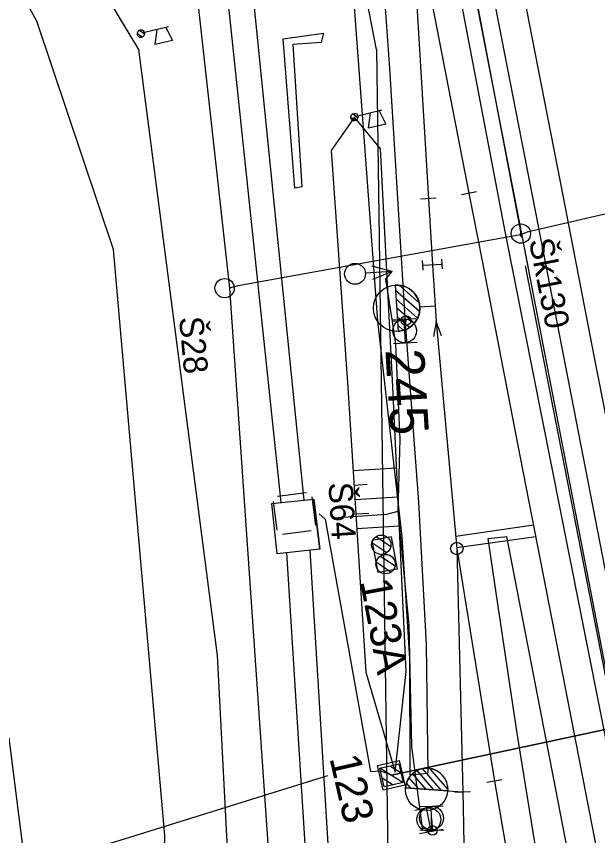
# Model space of a CAD drawing. Extents: x -545846 to -545044, y -1122650 to -1119108.
# Drawn here: x -545637.44 to -545607.35, y -1119789.85 to -1119747.46 of the extents above; entities that cross this region are included whole.
import ezdxf

# ---------------------------------------------------------------- set-up
doc = ezdxf.new("R2010")
doc.units = 0
for name, color, linetype in [('osvětlené plochy-hodnota-obrys', 7, 'Continuous'), ('Vrstva 1', 7, 'Continuous'), ('Vrstva 1 - Koleje', 7, 'Continuous'), ('Vrstva 11 - Trakce', 7, 'Continuous'), ('Vrstva 12 - Trakce zaklady', 7, 'Continuous'), ('Vrstva 17', 7, 'Continuous'), ('Vrstva 2', 7, 'Continuous'), ('Vrstva 2 - Vyhybky', 7, 'Continuous'), ('Vrstva 25', 7, 'Continuous'), ('Vrstva 26', 7, 'Continuous'), ('Vrstva 27', 7, 'Continuous'), ('Vrstva 28 - zabzar', 7, 'Continuous'), ('Vrstva 3', 7, 'Continuous'), ('Vrstva 3 - Lisy - Pocitaci body', 7, 'Continuous'), ('Vrstva 33', 7, 'Continuous'), ('Vrstva 34', 7, 'Continuous'), ('Vrstva 35', 7, 'Continuous'), ('Vrstva 36', 7, 'Continuous'), ('Vrstva 4 - Teren - stezky - prechody - plochy', 7, 'Continuous'), ('Vrstva 43', 7, 'Continuous'), ('Vrstva 44', 7, 'Continuous'), ('Vrstva 48', 7, 'Continuous'), ('Vrstva 49', 7, 'Continuous'), ('Vrstva 62', 7, 'Continuous'), ('Vrstva 63', 7, 'Continuous'), ('Vrstva 7 - Namezniky-vystroj', 7, 'Continuous')]:
    doc.layers.add(name, color=color, linetype=linetype)

msp = doc.modelspace()

# ---------------------------------------------------------------- linework, layer by layer
at = {"layer": 'osvětlené plochy-hodnota-obrys'}
for points in [[(-545610.895, -1119760.665), (-545622.836, -1119699.488), (-545637.26, -1119626.872), (-545653.542, -1119543.449), (-545716.386, -1119223.717)], [(-545618.794, -1119749.17), (-545664.282, -1119515.639)], [(-545618.794, -1119749.17), (-545617.001, -1119876.724)], [(-545611.105, -1119760.367), (-545492.389, -1120368.615), (-545475.582, -1120447.487)]]:
    msp.add_lwpolyline(points, dxfattribs=at)
at = {"layer": 'Vrstva 1'}
for points in [[(-545612.685, -1119787.025), (-545611.094, -1119796.357), (-545607.898, -1119813.098), (-545602.376, -1119841.635), (-545599.033, -1119858.8), (-545594.075, -1119884.173), (-545590.564, -1119902.118), (-545586.815, -1119921.29), (-545582.879, -1119941.487), (-545579.286, -1119959.902), (-545575.686, -1119978.306), (-545572.135, -1119996.454), (-545569.055, -1120012.422), (-545565.503, -1120030.558), (-545561.469, -1120051.222), (-545557.681, -1120070.616), (-545552.89, -1120095.213)], [(-545614.338, -1119787.583), (-545614.32, -1119788.383), (-545614.101, -1119799.744), (-545613.855, -1119812.402)]]:
    msp.add_lwpolyline(points, dxfattribs=at)
at = {"layer": 'Vrstva 1 - Koleje'}
for points in [[(-545620.04, -1119700.93), (-545618.466, -1119708.981), (-545618.287, -1119709.904), (-545617.707, -1119712.885), (-545616.218, -1119720.514), (-545614.817, -1119727.693), (-545612.814, -1119737.973), (-545610.755, -1119748.533), (-545609.137, -1119756.825), (-545607.54, -1119765.023), (-545606.208, -1119771.849), (-545604.163, -1119782.329), (-545602.108, -1119792.879), (-545600.005, -1119803.67), (-545598.048, -1119813.712), (-545596.051, -1119823.937), (-545594.041, -1119834.228), (-545591.245, -1119848.57), (-545589.268, -1119858.708), (-545587.271, -1119868.949), (-545585.312, -1119878.984), (-545583.448, -1119888.544), (-545581.461, -1119898.732)], [(-545619.495, -1119728.51), (-545619.342, -1119729.295), (-545617.081, -1119740.889), (-545616.115, -1119756.897), (-545615.896, -1119760.311), (-545615.76, -1119762.434)], [(-545619.495, -1119728.51), (-545619.342, -1119729.295), (-545617.081, -1119740.889), (-545614.014, -1119756.616), (-545613.347, -1119760.026), (-545611.356, -1119770.277), (-545609.291, -1119780.868), (-545607.284, -1119791.169), (-545605.791, -1119798.836), (-545605.539, -1119800.128), (-545603.55, -1119810.316), (-545601.73, -1119819.637), (-545599.797, -1119829.553), (-545597.8, -1119839.791), (-545595.924, -1119849.399), (-545593.688, -1119860.879), (-545591.957, -1119869.777), (-545589.995, -1119879.817), (-545588.126, -1119889.394), (-545586.206, -1119899.252)], [(-545615.76, -1119762.434), (-545615.705, -1119763.242), (-545614.641, -1119774.995), (-545612.699, -1119787.025)], [(-545615.76, -1119762.434), (-545615.705, -1119763.242), (-545614.641, -1119774.995), (-545614.338, -1119787.597)]]:
    msp.add_lwpolyline(points, dxfattribs=at)
at = {"layer": 'Vrstva 11 - Trakce'}
for p, q in [((-545619.036, -1119774.681), (-545618.272, -1119775.204)), ((-545618.818, -1119774.376), (-545618.065, -1119774.892)), ((-545618.592, -1119775.381), (-545617.839, -1119775.897)), ((-545618.81, -1119775.686), (-545618.046, -1119776.209)), ((-545618.618, -1119786.347), (-545617.425, -1119787.099)), ((-545618.102, -1119786.23), (-545617.543, -1119786.582)), ((-545618.505, -1119786.862), (-545617.939, -1119787.219))]:
    msp.add_line(p, q, dxfattribs=at)
msp.add_lwpolyline([(-545549.18, -1119771.986), (-545573.653, -1119777.088), (-545592.324, -1119781.23), (-545618.023, -1119786.725)], dxfattribs=at)
msp.add_lwpolyline([(-545617.646, -1119786.127), (-545617.425, -1119787.102), (-545618.4, -1119787.323), (-545618.621, -1119786.348)], close=True, dxfattribs=at)
for centre in [(-545618.553, -1119774.795), (-545618.327, -1119775.8)]:
    msp.add_circle(centre, 0.5, dxfattribs=at)
at = {"layer": 'Vrstva 12 - Trakce zaklady'}
for p, q in [((-545618.038, -1119774.387), (-545619.021, -1119774.57)), ((-545618.71, -1119776.236), (-545619.021, -1119774.57)), ((-545618.038, -1119774.387), (-545617.727, -1119776.053)), ((-545617.727, -1119776.053), (-545618.71, -1119776.236)), ((-545618.744, -1119786.214), (-545617.624, -1119785.963)), ((-545617.333, -1119787.239), (-545618.454, -1119787.491))]:
    msp.add_line(p, q, dxfattribs=at)
for points in [[(-545618.744, -1119786.214), (-545617.624, -1119785.963), (-545617.333, -1119787.239), (-545618.454, -1119787.491), (-545618.744, -1119786.214)], [(-545617.624, -1119785.963), (-545617.624, -1119785.963), (-545617.333, -1119787.239), (-545617.333, -1119787.239)]]:
    msp.add_lwpolyline(points, dxfattribs=at)
at = {"layer": 'Vrstva 17'}
msp.add_lwpolyline([(-545622.664, -1119756.289), (-545623.027, -1119756.353), (-545623.639, -1119748.623), (-545621.55, -1119748.325), (-545621.666, -1119748.822), (-545623.125, -1119748.912)], close=True, dxfattribs=at)
at = {"layer": 'Vrstva 2'}
for p, q in [((-545615.823, -1119787.482), (-545616.697, -1119786.477)), ((-545615.426, -1119787.51), (-545616.41, -1119786.379)), ((-545615.108, -1119787.447), (-545616.042, -1119786.372)), ((-545616.616, -1119787.426), (-545617.116, -1119786.852)), ((-545616.22, -1119787.454), (-545616.931, -1119786.637)), ((-545615.108, -1119787.532), (-545617.298, -1119787.379)), ((-545617.298, -1119787.379), (-545615.108, -1119787.531)), ((-545617.014, -1119787.398), (-545617.248, -1119787.129)), ((-545615.108, -1119787.531), (-545615.108, -1119787.532)), ((-545615.107, -1119787.532), (-545614.338, -1119787.583))]:
    msp.add_line(p, q, dxfattribs=at)
msp.add_lwpolyline([(-545614.338, -1119787.583), (-545614.32, -1119788.383), (-545614.101, -1119799.744), (-545613.855, -1119812.402)], dxfattribs=at)
msp.add_circle((-545616.209, -1119787.454), 1.097, dxfattribs=at)
msp.add_arc((-545616.203, -1119787.455), 1.098, 356.042, 176.0028, dxfattribs=at)
at = {"layer": 'Vrstva 2 - Vyhybky'}
for p, q in [((-545615.716, -1119756.873), (-545616.514, -1119756.921)), ((-545613.621, -1119756.539), (-545614.407, -1119756.693)), ((-545617.833, -1119761.364), (-545617.679, -1119763.759)), ((-545616.588, -1119762.291), (-545617.634, -1119761.371)), ((-545616.571, -1119762.732), (-545617.815, -1119761.638)), ((-545616.672, -1119763.07), (-545617.786, -1119762.089)), ((-545616.847, -1119763.341), (-545617.757, -1119762.541)), ((-545616.558, -1119762.485), (-545615.76, -1119762.434)), ((-545617.089, -1119763.556), (-545617.728, -1119762.993)), ((-545617.403, -1119763.706), (-545617.699, -1119763.444)), ((-545612.304, -1119786.961), (-545613.094, -1119787.089)), ((-545613.938, -1119787.587), (-545614.738, -1119787.607))]:
    msp.add_line(p, q, dxfattribs=at)
for points in [[(-545619.495, -1119728.51), (-545619.342, -1119729.295), (-545617.081, -1119740.889), (-545614.014, -1119756.616)], [(-545617.081, -1119740.889), (-545616.115, -1119756.897)], [(-545615.76, -1119762.434), (-545615.705, -1119763.242), (-545614.641, -1119774.995), (-545612.699, -1119787.025)], [(-545615.429, -1119763.993), (-545615.705, -1119763.242), (-545615.842, -1119764.03)], [(-545614.641, -1119774.995), (-545614.338, -1119787.597)]]:
    msp.add_lwpolyline(points, dxfattribs=at)
for centre, radius in [((-545617.756, -1119762.562), 1.2), ((-545614.641, -1119774.995), 0.32)]:
    msp.add_circle(centre, radius, dxfattribs=at)
msp.add_arc((-545617.756, -1119762.562), 1.2, 273.6636, 93.6636, dxfattribs=at)
at = {"layer": 'Vrstva 25'}
msp.add_lwpolyline([(-545618.023, -1119786.725), (-545592.324, -1119781.23)], dxfattribs=at)
at = {"layer": 'Vrstva 26'}
msp.add_lwpolyline([(-545621.764, -1119773.204), (-545621.45, -1119773.476), (-545619.108, -1119786.527), (-545618.583, -1119786.498), (-545618.023, -1119786.725)], dxfattribs=at)
at = {"layer": 'Vrstva 27'}
for p, q in [((-545617.269, -1119763.225), (-545617.271, -1119763.175)), ((-545615.9, -1119789.555), (-545615.9, -1119789.605))]:
    msp.add_line(p, q, dxfattribs=at)
for centre in [(-545617.27, -1119763.2), (-545615.9, -1119789.58)]:
    msp.add_circle(centre, 0.25, dxfattribs=at)
at = {"layer": 'Vrstva 28 - zabzar'}
for points in [[(-545615.95, -1119788.94), (-545615.9, -1119789.58), (-545616.42, -1119789.46), (-545616.97, -1119785.24), (-545617.11, -1119778.96), (-545617.68, -1119773.06), (-545617.58, -1119769.34), (-545617.79, -1119764.44), (-545617.97, -1119763.25), (-545618.31, -1119761.05), (-545617.99, -1119760.67)], [(-545617.34, -1119763.74), (-545617.27, -1119763.2), (-545617.97, -1119763.25)], [(-545621.03, -1119773.4), (-545618.27, -1119773.21), (-545617.68, -1119773.06)]]:
    msp.add_lwpolyline(points, dxfattribs=at)
at = {"layer": 'Vrstva 3'}
for p, q in [((-545616.813, -1119788.532), (-545615.604, -1119788.295)), ((-545615.971, -1119789.622), (-545616.209, -1119788.414)), ((-545616.576, -1119789.741), (-545615.367, -1119789.504))]:
    msp.add_line(p, q, dxfattribs=at)
msp.add_circle((-545616.091, -1119789.016), 0.616, dxfattribs=at)
at = {"layer": 'Vrstva 3 - Lisy - Pocitaci body'}
for p, q in [((-545616.38, -1119760.59), (-545616.41, -1119760.091)), ((-545616.395, -1119760.341), (-545615.397, -1119760.281)), ((-545615.382, -1119760.531), (-545615.412, -1119760.032)), ((-545617.99, -1119760.67), (-545619.368, -1119760.752)), ((-545617.99, -1119760.67), (-545619.044, -1119760.387)), ((-545617.99, -1119760.67), (-545619.003, -1119761.076)), ((-545617.99, -1119763.16), (-545616.76, -1119763.09)), ((-545617.305, -1119764.355), (-545617.375, -1119763.125)), ((-545617.92, -1119764.39), (-545616.69, -1119764.32)), ((-545616.58, -1119788.338), (-545615.348, -1119788.31)), ((-545615.936, -1119789.556), (-545615.964, -1119788.324)), ((-545616.552, -1119789.57), (-545615.32, -1119789.542))]:
    msp.add_line(p, q, dxfattribs=at)
for centre, radius in [((-545619.909, -1119760.783), 0.542), ((-545617.341, -1119763.738), 0.616), ((-545615.951, -1119788.938), 0.616)]:
    msp.add_circle(centre, radius, dxfattribs=at)
at = {"layer": 'Vrstva 33'}
for p, q in [((-545629.57, -1119748), (-545630.815, -1119748.298)), ((-545631.17, -1119748.347), (-545630.919, -1119748.53)), ((-545631.069, -1119748.177), (-545630.813, -1119748.364)), ((-545630.258, -1119748.921), (-545630.149, -1119748.138)), ((-545629.704, -1119748.032), (-545629.367, -1119748.708)), ((-545629.367, -1119748.708), (-545630.258, -1119748.921)), ((-545620.124, -1119752.671), (-545619.873, -1119752.854)), ((-545620.023, -1119752.501), (-545619.767, -1119752.688)), ((-545618.524, -1119752.324), (-545619.769, -1119752.622)), ((-545619.212, -1119753.245), (-545619.103, -1119752.462)), ((-545618.658, -1119752.356), (-545618.321, -1119753.032)), ((-545618.321, -1119753.032), (-545619.212, -1119753.245))]:
    msp.add_line(p, q, dxfattribs=at)
for centre, major_axis in [((-545630.991, -1119748.352), (-0.044, -0.195)), ((-545630.991, -1119748.352), (-0.044, -0.196)), ((-545619.945, -1119752.676), (-0.044, -0.195)), ((-545619.945, -1119752.676), (-0.044, -0.196))]:
    msp.add_ellipse(centre, major_axis=major_axis, ratio=0.897978, dxfattribs=at)
at = {"layer": 'Vrstva 34'}
for p, q in [((-545623.918, -1119772.283), (-545622.43, -1119772.095)), ((-545623.947, -1119774.05), (-545624.135, -1119772.562)), ((-545622.151, -1119772.312), (-545621.963, -1119773.8)), ((-545622.18, -1119774.079), (-545623.668, -1119774.267))]:
    msp.add_line(p, q, dxfattribs=at)
at = {"layer": 'Vrstva 35'}
for p, q in [((-545622.536, -1119772.489), (-545626.966, -1119728.759)), ((-545623.729, -1119772.61), (-545628.334, -1119728.982)), ((-545619.482, -1119820.241), (-545622.229, -1119775.076)), ((-545620.613, -1119820.304), (-545623.445, -1119775.209))]:
    msp.add_line(p, q, dxfattribs=at)
at = {"layer": 'Vrstva 36'}
for points in [[(-545624.224, -1119772.661), (-545622.036, -1119772.438), (-545621.728, -1119775.022), (-545623.938, -1119775.263), (-545624.224, -1119772.661)], [(-545624.224, -1119772.661), (-545622.036, -1119772.438), (-545622.036, -1119772.438)], [(-545621.728, -1119775.022), (-545622.036, -1119772.438)], [(-545623.938, -1119775.263), (-545624.224, -1119772.661), (-545624.224, -1119772.661)], [(-545621.728, -1119775.022), (-545621.728, -1119775.022), (-545623.938, -1119775.263), (-545623.938, -1119775.263)]]:
    msp.add_lwpolyline(points, dxfattribs=at)
at = {"layer": 'Vrstva 4 - Teren - stezky - prechody - plochy'}
for points in [[(-545668.116, -1119499.514), (-545665.721, -1119507.929), (-545662.615, -1119519.622), (-545659.148, -1119534.332), (-545655.765, -1119550.675), (-545641.939, -1119621.169), (-545637.993, -1119641.248), (-545631.568, -1119675.037), (-545626.43, -1119701.616), (-545620.933, -1119729.23), (-545619.776, -1119736.256), (-545618.414, -1119746.042), (-545618.118, -1119750.155), (-545617.307, -1119763.323), (-545616.619, -1119772.592), (-545616.223, -1119779.957), (-545616.135, -1119786.617)], [(-545488.754, -1120379.549), (-545491.925, -1120363.788), (-545496.278, -1120342.782), (-545500.506, -1120321.731), (-545508.599, -1120280.828), (-545518.82, -1120228.621), (-545531.029, -1120165.923), (-545540.626, -1120116.248), (-545552.245, -1120057.042), (-545557.488, -1120030.03), (-545563.439, -1119999.512), (-545572.128, -1119954.79), (-545581.61, -1119906.246), (-545591.458, -1119855.639), (-545600.962, -1119806.943), (-545610.434, -1119758.233), (-545616.648, -1119726.461), (-545621.696, -1119701.088), (-545622.533, -1119696.196), (-545623.462, -1119696.331)], [(-545490.916, -1120379.972), (-545493.99, -1120364.147), (-545502.163, -1120322.09), (-545510.164, -1120281.035), (-545520.235, -1120229.023), (-545532.517, -1120166.017), (-545542.296, -1120116.028), (-545553.809, -1120057.082), (-545558.932, -1120030.597), (-545564.969, -1119999.794), (-545573.753, -1119955.036), (-545583.127, -1119906.578), (-545593.017, -1119855.856), (-545602.553, -1119806.891), (-545612.123, -1119758.671), (-545618.333, -1119726.047), (-545620.676, -1119713.873), (-545622.612, -1119701.558), (-545623.462, -1119696.331)], [(-545627.31, -1119704.719), (-545625.835, -1119712.063), (-545622.496, -1119729.428), (-545620.183, -1119743.94), (-545619.945, -1119747.203), (-545618.749, -1119763.231), (-545617.479, -1119774.393), (-545617.097, -1119780.69), (-545617.068, -1119786.701), (-545616.135, -1119786.617)], [(-545495.535, -1120380.876), (-545498.596, -1120365.093), (-545507.092, -1120321.572), (-545515.017, -1120281.173), (-545524.994, -1120229.535), (-545536.771, -1120169.47), (-545546.676, -1120118.787), (-545557.312, -1120064.079), (-545563.312, -1120033.308), (-545569.884, -1119999.645), (-545578.452, -1119955.82), (-545587.921, -1119907.338), (-545597.812, -1119856.591), (-545607.33, -1119807.681), (-545610.119, -1119793.19), (-545611.535, -1119784.447), (-545612.6, -1119777.287), (-545613.018, -1119774.47), (-545612.047, -1119774.376)], [(-545493.924, -1120380.561), (-545496.951, -1120365.161), (-545505.376, -1120321.611), (-545513.278, -1120281.443), (-545523.478, -1120229.493), (-545535.102, -1120169.56), (-545545.054, -1120118.579), (-545554.55, -1120069.937), (-545561.701, -1120033.181), (-545568.213, -1119999.317), (-545576.806, -1119955.508), (-545586.262, -1119907.136), (-545605.677, -1119807.326), (-545612.047, -1119774.376)]]:
    msp.add_lwpolyline(points, dxfattribs=at)
at = {"layer": 'Vrstva 43'}
for centre in [(-545611.326, -1119758.703), (-545626.661, -1119761.524)]:
    msp.add_circle(centre, 0.5, dxfattribs=at)
at = {"layer": 'Vrstva 44'}
for points in [[(-545654.9, -1119582.222), (-545645.965, -1119631.818), (-545637.145, -1119681.816), (-545629.836, -1119730.566), (-545626.416, -1119761.521), (-545622.849, -1119813.009), (-545619.592, -1119863.304), (-545618.858, -1119914.175), (-545618.881, -1119950.565), (-545618.715, -1119963.415), (-545629.02, -1119997.179)], [(-545622.746, -1119648.835), (-545613.361, -1119699.038), (-545602.122, -1119756.581), (-545611.004, -1119758.624), (-545611.36, -1119758.757)], [(-545632.322, -1119650.948), (-545622.321, -1119700.988), (-545611.338, -1119758.596), (-545611.36, -1119758.757), (-545611.449, -1119758.784)], [(-545611.449, -1119758.783), (-545625.968, -1119761.4), (-545626.416, -1119761.521)], [(-545592.27, -1119855.857), (-545601.824, -1119807.634), (-545611.247, -1119758.903), (-545611.36, -1119758.757)]]:
    msp.add_lwpolyline(points, dxfattribs=at)
at = {"layer": 'Vrstva 48'}
for p, q in [((-545620.004, -1119770.96), (-545617.762, -1119770.818)), ((-545619.956, -1119771.708), (-545619.287, -1119771.666)), ((-545619.909, -1119772.457), (-545617.69, -1119772.317)), ((-545619.862, -1119773.205), (-545619.199, -1119773.164)), ((-545619.814, -1119773.954), (-545617.618, -1119773.815))]:
    msp.add_line(p, q, dxfattribs=at)
at = {"layer": 'Vrstva 49'}
for points in [[(-545619.945, -1119752.676), (-545621.148, -1119754.41), (-545620.275, -1119766.663), (-545619.345, -1119781.385), (-545617.84, -1119786.559)], [(-545617.84, -1119786.559), (-545617.258, -1119781.35), (-545617.962, -1119766.626), (-545618.589, -1119754.32), (-545619.945, -1119752.676)]]:
    msp.add_lwpolyline(points, dxfattribs=at)
at = {"layer": 'Vrstva 62'}
for points in [[(-545640.514, -1119731.132), (-545640.565, -1119731.562), (-545637.52, -1119738.574), (-545631.121, -1119749.176), (-545627.046, -1119780.523), (-545625.616, -1119808.19), (-545622.475, -1119817.927), (-545620.564, -1119842.07), (-545627.793, -1119850.696), (-545627.914, -1119866.869), (-545625.298, -1119872.204), (-545622.371, -1119881.231), (-545621.372, -1119899.088), (-545619.713, -1119906.036), (-545619.415, -1119919.615), (-545622.171, -1119926.525), (-545621.036, -1119950.949)], [(-545638.201, -1119873.676), (-545634.87, -1119872.217), (-545634.795, -1119868.379), (-545631.845, -1119861.885), (-545633.332, -1119850.19), (-545628.466, -1119836.59), (-545630.287, -1119812.477), (-545629.754, -1119789.831), (-545632.421, -1119759.531), (-545636.379, -1119747.707), (-545644.025, -1119733.886)], [(-545630.132, -1119845.654), (-545637.813, -1119784.782)]]:
    msp.add_lwpolyline(points, dxfattribs=at)
at = {"layer": 'Vrstva 63'}
msp.add_line((-545621.33, -1119786.748), (-545668.531, -1119801.411), dxfattribs=at)
at = {"layer": 'Vrstva 7 - Namezniky-vystroj'}
for p, q in [((-545614.7, -1119774.346), (-545610.674, -1119773.773)), ((-545614.646, -1119774.945), (-545610.559, -1119774.363))]:
    msp.add_line(p, q, dxfattribs=at)

# ---------------------------------------------------------------- texts
at = {"layer": 'Vrstva 11 - Trakce'}
for s, rotation, p in [('123A', 280.574, (-545619.654, -1119776.677)), ('123', 282.7946, (-545621.24, -1119785.827))]:
    msp.add_text(s, height=1.6, rotation=rotation, dxfattribs=at).set_placement(p)
at = {"layer": 'Vrstva 2 - Vyhybky'}
msp.add_text('245', height=2, rotation=273.4551, dxfattribs=at).set_placement((-545618.343, -1119764.719))
at = {"layer": 'Vrstva 34'}
msp.add_text('Š64', height=1.25, rotation=273.4482, dxfattribs=at).set_placement((-545621.288, -1119771.594))
at = {"layer": 'Vrstva 43'}
for s, rotation, p in [('Šk130', 280.9998, (-545610.911, -1119759.054)), ('Š28', 275.321, (-545629.023, -1119763.042))]:
    msp.add_text(s, height=1.25, rotation=rotation, dxfattribs=at).set_placement(p)

doc.saveas('drawing.dxf')
